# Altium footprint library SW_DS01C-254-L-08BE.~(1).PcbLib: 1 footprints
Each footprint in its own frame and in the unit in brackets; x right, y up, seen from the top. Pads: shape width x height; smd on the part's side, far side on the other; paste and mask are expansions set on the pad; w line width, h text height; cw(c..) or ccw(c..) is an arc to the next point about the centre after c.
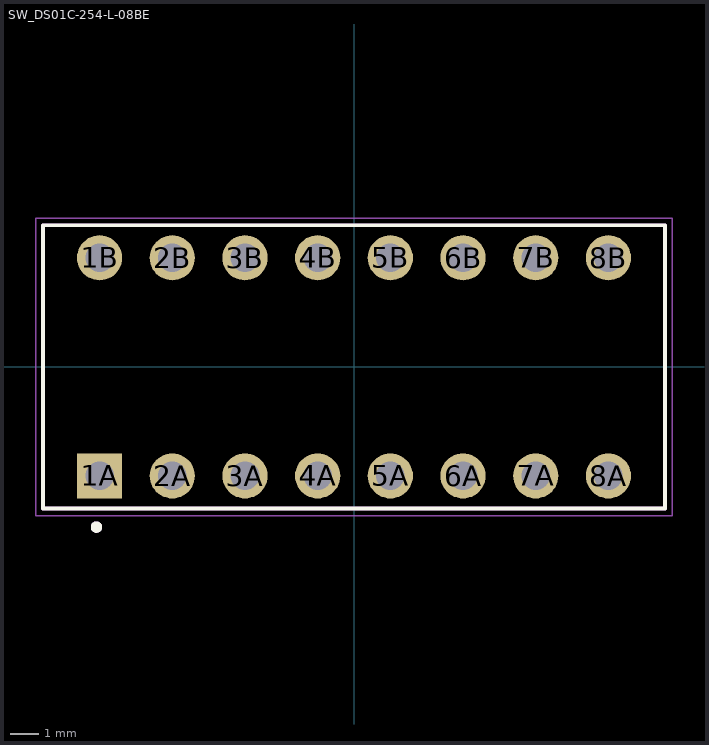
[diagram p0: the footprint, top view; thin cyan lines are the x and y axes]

## SW_DS01C-254-L-08BE [mm]
height 7
pads (16):
  rect 1.58x1.58 / inner round 1.58 / far side rect 1.58x1.58 hole 1: 1A(-8.89,-3.81)
  round 1.58 hole 1: 1B(-8.89,3.81) 2A(-6.35,-3.81) 2B(-6.35,3.81) 3A(-3.81,-3.81) 3B(-3.81,3.81) 4A(-1.27,-3.81) 4B(-1.27,3.81) 5A(1.27,-3.81) 5B(1.27,3.81) 6A(3.81,-3.81) 6B(3.81,3.81) 7A(6.35,-3.81) 7B(6.35,3.81) 8A(8.89,-3.81) 8B(8.89,3.81)
Top Overlay:
  circle w0.2: c-9,-5.6 r0.1
  lines w0.127: -10.87,-4.95 -10.87,4.95 10.87,4.95 10.87,-4.95 -10.87,-4.95
Assembly Top:
  circle w0.2: c-9,-5.6 r0.1
  lines w0.127: -10.87,-4.95 -10.87,4.95 10.87,4.95 10.87,-4.95 -10.87,-4.95
Courtyard Top:
  lines w0.05: -11.12,-5.2 -11.12,5.2 11.12,5.2 11.12,-5.2 -11.12,-5.2
3D body "step_temp.STEP": height 5.18, standoff -5.18, extent -4.95,-4.625 4.95,17.115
